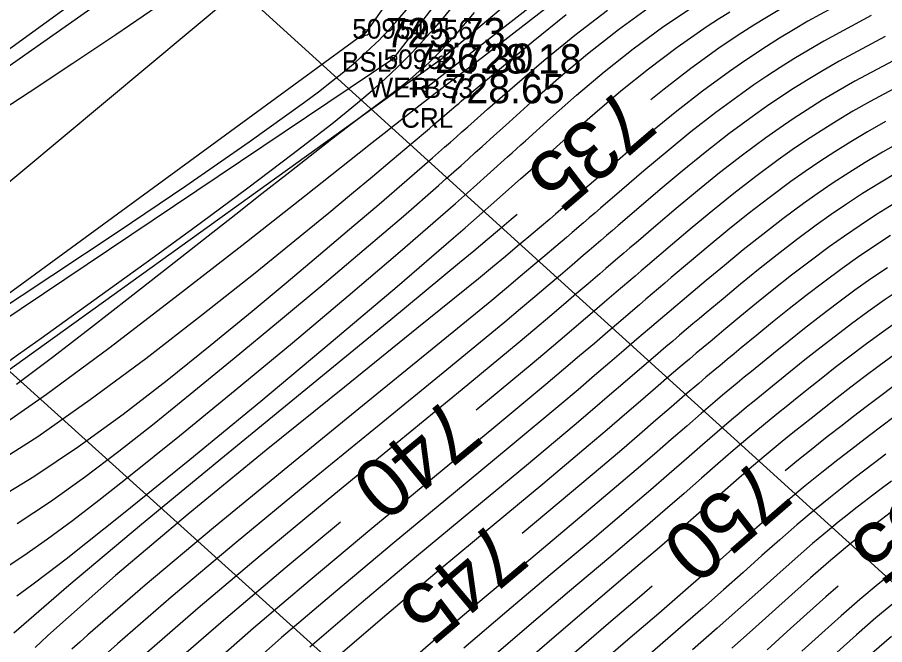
# Model space of a CAD drawing. Extents: x 1378535 to 1380697, y 997729 to 1000024.
# Drawn here: x 1379681.73 to 1379726.06, y 998932.79 to 998964.85 of the extents above; entities that cross this region are included whole.
import ezdxf

# ---------------------------------------------------------------- set-up
doc = ezdxf.new("R2010")
doc.units = 0
for name, color, linetype in [('RD_DTM_BkLn1', 7, 'Continuous'), ('RD_DTM_BkLn2', 7, 'Continuous'), ('RD_DTM_BkLn_txCode', 7, 'Continuous'), ('RD_DTM_Major1', 7, 'Continuous'), ('RD_DTM_Major1_Lbl', 7, 'Continuous'), ('RD_DTM_Minor1', 7, 'Continuous'), ('RD_EX_Bridge', 7, 'Continuous'), ('RD_EX_H2O', 7, 'Continuous'), ('RD_EX_H2O_txCode', 7, 'Continuous'), ('RD_EX_TX_H2O_ELEV', 7, 'Continuous'), ('RD_EX_TX_Misc_ELEV', 7, 'Continuous'), ('RD_SMD_Locator', 7, 'Continuous')]:
    doc.layers.add(name, color=color, linetype=linetype)

msp = doc.modelspace()

# ---------------------------------------------------------------- linework, layer by layer
at = {"layer": 'RD_DTM_BkLn1'}
msp.add_lwpolyline([(1379671.069, 998947.908), (1379694.884, 998967.78), (1379723.442, 999002.448), (1379771.255, 999073.041), (1379827.632, 999138.855), (1379861.249, 999179.195), (1379915.357, 999192.54), (1379973.258, 999207.681), (1380032.706, 999223.017), (1380054.696, 999270.258), (1380073.859, 999314.517)], dxfattribs=at)
at = {"layer": 'RD_DTM_BkLn2'}
for points in [[(1380068.121, 999316.651), (1380049.657, 999274.82), (1380028.513, 999225.034), (1379966.47, 999214.136), (1379918.102, 999198.529), (1379857.342, 999182.9), (1379822.296, 999142.387), (1379766.345, 999075.773), (1379728.069, 999017.429), (1379693.219, 998970.733), (1379663.886, 998950.121)], [(1380081.016, 999311.458), (1380061.411, 999264.141), (1380033.797, 999220.561), (1379978.164, 999199.192), (1379919.041, 999191.309), (1379864.05, 999174.436), (1379831.301, 999133.028), (1379774.735, 999068.751), (1379734.541, 999013.539), (1379699.544, 998964.07), (1379671.775, 998943.782)], [(1379714.915, 998970.843), (1379709.288, 998967.69), (1379703.428, 998962.728), (1379674.221, 998941.737), (1379670.73, 998937.246)]]:
    msp.add_lwpolyline(points, dxfattribs=at)
at = {"layer": 'RD_DTM_Major1'}
for points in [[(1379720.692, 998965.242), (1379720.02, 998964.845), (1379719.377, 998964.452), (1379718.758, 998964.06), (1379718.159, 998963.666), (1379717.575, 998963.268), (1379716.149, 998962.241), (1379714.78, 998961.186), (1379714.107, 998960.638)], [(1379680.379, 998941.917), (1379682.77, 998943.437), (1379685.45, 998945.314), (1379688.286, 998947.419), (1379691.142, 998949.625), (1379693.883, 998951.801), (1379696.373, 998953.82), (1379697.642, 998954.861), (1379698.805, 998955.823), (1379699.881, 998956.72), (1379700.889, 998957.569), (1379701.851, 998958.382), (1379702.786, 998959.176), (1379703.011, 998959.367), (1379703.237, 998959.559), (1379703.463, 998959.752), (1379703.922, 998960.142), (1379704.154, 998960.339), (1379704.286, 998960.451), (1379704.418, 998960.563), (1379704.552, 998960.677), (1379704.687, 998960.791), (1379704.823, 998960.906), (1379704.961, 998961.023), (1379706.465, 998962.288), (1379708.085, 998963.628), (1379709.776, 998964.995)], [(1379727.484, 998961.706), (1379725.315, 998960.552), (1379724.431, 998960.047), (1379723.598, 998959.55), (1379722.809, 998959.057), (1379722.055, 998958.565), (1379721.329, 998958.071), (1379720.623, 998957.571), (1379719.47, 998956.718), (1379718.351, 998955.85), (1379717.269, 998954.978), (1379716.224, 998954.113), (1379715.218, 998953.263), (1379713.933, 998952.168), (1379713.616, 998951.898), (1379713.3, 998951.629), (1379712.983, 998951.358), (1379712.664, 998951.085), (1379712.339, 998950.807), (1379711.74, 998950.292), (1379711.107, 998949.749), (1379710.432, 998949.17), (1379709.701, 998948.547), (1379708.906, 998947.873), (1379708.034, 998947.141), (1379705.266, 998944.843), (1379705.185, 998944.776)], [(1379707.277, 998954.778), (1379706.968, 998954.514), (1379706.377, 998954.011), (1379705.745, 998953.477), (1379705.066, 998952.908), (1379704.333, 998952.296), (1379700.816, 998949.394), (1379692.309, 998942.428), (1379688.077, 998938.937), (1379684.363, 998935.823), (1379681.547, 998933.373)], [(1379726.362, 998953.699), (1379725.501, 998953.137), (1379724.675, 998952.575), (1379723.879, 998952.009), (1379722.947, 998951.323), (1379722.046, 998950.635), (1379721.176, 998949.951), (1379720.333, 998949.274), (1379719.518, 998948.608), (1379718.729, 998947.958), (1379718.367, 998947.66), (1379718.008, 998947.363), (1379717.649, 998947.066), (1379717.289, 998946.765), (1379716.925, 998946.46), (1379716.554, 998946.146), (1379715.867, 998945.557), (1379715.14, 998944.93), (1379714.364, 998944.257), (1379713.528, 998943.533), (1379712.62, 998942.752), (1379711.631, 998941.908), (1379709.422, 998940.051), (1379707.529, 998938.473)], [(1379726.493, 998945.983), (1379725.793, 998945.463), (1379725.116, 998944.952), (1379724.459, 998944.447), (1379723.819, 998943.949), (1379723.191, 998943.456), (1379722.787, 998943.139), (1379722.385, 998942.821), (1379721.981, 998942.499), (1379721.573, 998942.17), (1379721.159, 998941.831), (1379720.975, 998941.678)], [(1379698.241, 998939.051), (1379695.409, 998936.7), (1379692.375, 998934.137), (1379689.851, 998931.935), (1379689.269, 998931.409), (1379688.739, 998930.918), (1379688.255, 998930.459), (1379687.812, 998930.027), (1379687.404, 998929.616), (1379687.025, 998929.222), (1379686.73, 998928.905), (1379686.446, 998928.592), (1379686.17, 998928.28), (1379685.897, 998927.964), (1379685.622, 998927.64), (1379685.342, 998927.305), (1379685.022, 998926.918), (1379684.327, 998926.072), (1379683.945, 998925.605), (1379683.536, 998925.104), (1379683.094, 998924.566), (1379681.167, 998922.234)], [(1379714.179, 998935.777), (1379713.655, 998935.328), (1379711.94, 998933.866), (1379710.187, 998932.366)], [(1379723.678, 998935.784), (1379723.052, 998935.239), (1379722.079, 998934.372), (1379721.077, 998933.466), (1379720.05, 998932.534)]]:
    msp.add_lwpolyline(points, dxfattribs=at)
at = {"layer": 'RD_DTM_Minor1'}
for points in [[(1379724.659, 998966.027), (1379722.137, 998964.652), (1379721.394, 998964.217), (1379720.687, 998963.788), (1379720.012, 998963.363), (1379719.363, 998962.939), (1379718.735, 998962.514), (1379718.122, 998962.084), (1379716.755, 998961.078), (1379715.436, 998960.049), (1379714.164, 998959.011), (1379712.939, 998957.978), (1379711.758, 998956.963), (1379710.622, 998955.979), (1379710.343, 998955.739), (1379710.066, 998955.5), (1379709.789, 998955.262), (1379709.511, 998955.023), (1379709.23, 998954.783), (1379708.946, 998954.541), (1379708.422, 998954.096), (1379707.875, 998953.634), (1379707.296, 998953.148), (1379706.677, 998952.633), (1379706.012, 998952.083), (1379705.291, 998951.491), (1379702.15, 998948.945), (1379698.441, 998945.959), (1379694.449, 998942.73), (1379690.455, 998939.453), (1379686.742, 998936.325), (1379683.592, 998933.542), (1379683.261, 998933.237), (1379682.943, 998932.94), (1379682.635, 998932.649)], [(1379680.899, 998936.59), (1379682.062, 998937.356), (1379683.27, 998938.205), (1379684.541, 998939.145), (1379685.893, 998940.182), (1379687.346, 998941.324), (1379690.006, 998943.46), (1379692.863, 998945.797), (1379695.785, 998948.222), (1379698.64, 998950.622), (1379701.294, 998952.884), (1379703.617, 998954.895), (1379704.117, 998955.334), (1379705.05, 998956.159), (1379705.915, 998956.932), (1379706.787, 998957.717), (1379707.014, 998957.921), (1379707.241, 998958.126), (1379707.467, 998958.331), (1379707.695, 998958.537), (1379708.976, 998959.691), (1379710.314, 998960.871), (1379711.72, 998962.06), (1379713.202, 998963.24), (1379714.77, 998964.395), (1379716.434, 998965.507)], [(1379688.861, 998965.379), (1379686.761, 998963.948), (1379684.566, 998962.485), (1379682.328, 998961.012), (1379680.102, 998959.554)], [(1379680.317, 998940.029), (1379682.577, 998941.389), (1379684.857, 998942.922), (1379687.134, 998944.579), (1379689.385, 998946.316), (1379691.589, 998948.085), (1379693.722, 998949.84), (1379695.459, 998951.285), (1379697.124, 998952.681), (1379698.712, 998954.023), (1379700.216, 998955.306), (1379701.631, 998956.525), (1379702.951, 998957.674), (1379703.257, 998957.943), (1379703.559, 998958.208), (1379703.858, 998958.471), (1379704.155, 998958.733), (1379704.451, 998958.995), (1379704.748, 998959.257), (1379705.081, 998959.552), (1379705.249, 998959.701), (1379705.419, 998959.85), (1379705.762, 998960.153), (1379707.152, 998961.371), (1379708.642, 998962.643), (1379710.222, 998963.937), (1379711.885, 998965.221)], [(1379680.392, 998949.615), (1379683.492, 998951.653), (1379686.886, 998953.909), (1379690.332, 998956.236), (1379693.583, 998958.485), (1379696.396, 998960.508), (1379697.122, 998961.051), (1379697.792, 998961.568), (1379698.412, 998962.065), (1379698.989, 998962.549), (1379699.529, 998963.028), (1379700.038, 998963.508), (1379700.217, 998963.685), (1379700.393, 998963.863), (1379700.566, 998964.043), (1379700.737, 998964.225), (1379700.906, 998964.41), (1379701.074, 998964.597), (1379701.797, 998965.455)], [(1379680.436, 998943.661), (1379683.208, 998945.598), (1379686.397, 998947.952), (1379689.797, 998950.544), (1379693.201, 998953.192), (1379696.406, 998955.713), (1379699.205, 998957.928), (1379699.858, 998958.445), (1379700.474, 998958.932), (1379701.06, 998959.394), (1379701.624, 998959.837), (1379702.171, 998960.265), (1379702.838, 998960.783), (1379703.098, 998960.985), (1379703.228, 998961.085), (1379703.359, 998961.185), (1379703.49, 998961.286), (1379703.563, 998961.342), (1379703.71, 998961.455), (1379703.931, 998961.625), (1379705.495, 998962.816), (1379707.112, 998964.053), (1379708.752, 998965.332)], [(1379680.71, 998946.87), (1379681.786, 998947.638), (1379682.937, 998948.462), (1379684.17, 998949.346), (1379686.376, 998950.931), (1379688.728, 998952.632), (1379691.137, 998954.389), (1379693.511, 998956.144), (1379695.76, 998957.838), (1379697.793, 998959.412), (1379698.526, 998959.996), (1379699.22, 998960.564), (1379699.883, 998961.129), (1379700.527, 998961.703), (1379701.159, 998962.299), (1379701.789, 998962.93), (1379702.206, 998963.368), (1379702.628, 998963.829), (1379703.06, 998964.316), (1379703.504, 998964.832), (1379703.963, 998965.381)], [(1379681.685, 998946.104), (1379683.515, 998947.49), (1379685.467, 998948.987), (1379687.484, 998950.548), (1379689.509, 998952.127), (1379691.485, 998953.677), (1379692.89, 998954.783), (1379694.23, 998955.84), (1379695.5, 998956.84), (1379696.692, 998957.774), (1379697.802, 998958.636), (1379698.822, 998959.417), (1379699.525, 998959.948), (1379700.181, 998960.44), (1379700.794, 998960.904), (1379701.371, 998961.352), (1379701.918, 998961.795), (1379702.44, 998962.244), (1379702.598, 998962.386), (1379702.754, 998962.531), (1379702.91, 998962.678), (1379703.064, 998962.828), (1379703.219, 998962.981), (1379703.374, 998963.139), (1379703.783, 998963.573), (1379704.201, 998964.042), (1379704.633, 998964.55), (1379705.085, 998965.099)], [(1379681.699, 998935.291), (1379682.468, 998935.853), (1379683.304, 998936.481), (1379684.22, 998937.184), (1379687.157, 998939.505), (1379690.551, 998942.256), (1379694.166, 998945.238), (1379697.771, 998948.252), (1379701.133, 998951.097), (1379704.018, 998953.575), (1379704.624, 998954.101), (1379705.192, 998954.597), (1379706.237, 998955.517), (1379707.452, 998956.595), (1379707.958, 998957.047), (1379709.955, 998958.829), (1379711.243, 998959.956), (1379712.581, 998961.089), (1379713.98, 998962.216), (1379715.447, 998963.322), (1379716.99, 998964.396), (1379717.558, 998964.768), (1379718.14, 998965.136)], [(1379681.713, 998938.982), (1379683.42, 998940.116), (1379685.15, 998941.353), (1379686.911, 998942.685), (1379688.714, 998944.102), (1379690.566, 998945.594), (1379692.811, 998947.426), (1379695.079, 998949.301), (1379697.314, 998951.169), (1379699.459, 998952.983), (1379701.456, 998954.694), (1379703.248, 998956.255), (1379703.647, 998956.607), (1379704.033, 998956.949), (1379704.408, 998957.283), (1379704.774, 998957.61), (1379705.134, 998957.934), (1379705.489, 998958.254), (1379705.687, 998958.432), (1379705.884, 998958.611), (1379706.081, 998958.789), (1379706.679, 998959.33), (1379707.995, 998960.516), (1379709.39, 998961.742), (1379710.874, 998962.986), (1379712.456, 998964.229), (1379714.145, 998965.449)], [(1379725.376, 998964.941), (1379722.943, 998963.627), (1379722.159, 998963.173), (1379721.417, 998962.725), (1379720.709, 998962.282), (1379720.03, 998961.84), (1379719.374, 998961.396), (1379718.734, 998960.947), (1379717.424, 998959.982), (1379716.157, 998958.996), (1379714.935, 998958.002), (1379713.756, 998957.012), (1379712.622, 998956.041), (1379711.533, 998955.1), (1379711.243, 998954.85), (1379710.956, 998954.602), (1379710.668, 998954.354), (1379710.089, 998953.857), (1379709.795, 998953.604), (1379709.252, 998953.14), (1379708.683, 998952.655), (1379708.079, 998952.144), (1379707.431, 998951.599), (1379706.732, 998951.015), (1379705.972, 998950.384), (1379702.93, 998947.892), (1379699.365, 998944.994), (1379695.549, 998941.886), (1379691.756, 998938.769), (1379688.259, 998935.839), (1379685.333, 998933.295), (1379684.915, 998932.918), (1379684.518, 998932.555)], [(1379726.08, 998963.863), (1379723.737, 998962.605), (1379722.917, 998962.133), (1379722.142, 998961.667), (1379721.406, 998961.207), (1379720.701, 998960.747), (1379720.02, 998960.285), (1379719.356, 998959.818), (1379718.102, 998958.893), (1379716.888, 998957.948), (1379715.714, 998956.996), (1379714.581, 998956.049), (1379713.491, 998955.119), (1379712.445, 998954.218), (1379712.144, 998953.96), (1379711.846, 998953.703), (1379711.549, 998953.448), (1379710.949, 998952.933), (1379710.643, 998952.671), (1379710.08, 998952.187), (1379709.487, 998951.681), (1379708.856, 998951.144), (1379708.178, 998950.569), (1379707.442, 998949.95), (1379706.638, 998949.28), (1379703.674, 998946.836), (1379700.221, 998944.012), (1379696.547, 998941.005), (1379692.915, 998938.009), (1379689.592, 998935.221), (1379686.842, 998932.837), (1379686.365, 998932.409)], [(1379726.782, 998962.785), (1379724.527, 998961.58), (1379723.674, 998961.091), (1379722.869, 998960.609), (1379722.106, 998960.131), (1379721.376, 998959.655), (1379720.672, 998959.177), (1379719.986, 998958.693), (1379718.784, 998957.804), (1379717.619, 998956.899), (1379716.491, 998955.987), (1379715.403, 998955.081), (1379714.356, 998954.192), (1379713.351, 998953.331), (1379713.04, 998953.065), (1379712.733, 998952.802), (1379712.426, 998952.539), (1379711.807, 998952.009), (1379711.492, 998951.739), (1379710.91, 998951.239), (1379710.297, 998950.713), (1379709.642, 998950.154), (1379708.937, 998949.555), (1379708.169, 998948.907), (1379707.33, 998948.203), (1379704.459, 998945.827), (1379701.138, 998943.099), (1379697.616, 998940.206), (1379694.143, 998937.331), (1379690.968, 998934.661), (1379688.342, 998932.379)], [(1379726.101, 998959.522), (1379725.188, 998959.003), (1379724.328, 998958.491), (1379723.514, 998957.983), (1379722.738, 998957.476), (1379721.99, 998956.967), (1379721.265, 998956.453), (1379720.158, 998955.634), (1379719.086, 998954.803), (1379718.047, 998953.97), (1379717.045, 998953.144), (1379716.079, 998952.333), (1379715.151, 998951.547), (1379714.822, 998951.268), (1379714.497, 998950.992), (1379714.172, 998950.717), (1379713.847, 998950.44), (1379713.519, 998950.16), (1379713.185, 998949.875), (1379712.568, 998949.346), (1379711.917, 998948.786), (1379711.221, 998948.188), (1379710.468, 998947.544), (1379709.647, 998946.846), (1379708.746, 998946.087), (1379706.087, 998943.873), (1379703.051, 998941.366), (1379699.851, 998938.722), (1379696.697, 998936.094), (1379693.799, 998933.637), (1379691.369, 998931.505)], [(1379726.886, 998958.491), (1379725.946, 998957.958), (1379725.06, 998957.433), (1379724.223, 998956.911), (1379723.424, 998956.389), (1379722.656, 998955.866), (1379721.912, 998955.337), (1379720.851, 998954.552), (1379719.823, 998953.758), (1379718.827, 998952.964), (1379717.866, 998952.176), (1379716.939, 998951.402), (1379716.047, 998950.652), (1379715.71, 998950.368), (1379715.376, 998950.086), (1379715.043, 998949.805), (1379714.372, 998949.236), (1379714.03, 998948.943), (1379713.396, 998948.399), (1379712.726, 998947.823), (1379712.01, 998947.206), (1379711.235, 998946.541), (1379710.39, 998945.821), (1379709.463, 998945.038), (1379706.914, 998942.911), (1379704.027, 998940.521), (1379700.991, 998938.006), (1379697.997, 998935.503), (1379695.235, 998933.151), (1379692.895, 998931.087)], [(1379726.703, 998956.914), (1379725.794, 998956.375), (1379724.933, 998955.839), (1379724.113, 998955.304), (1379723.326, 998954.767), (1379722.563, 998954.225), (1379721.547, 998953.473), (1379720.562, 998952.715), (1379719.609, 998951.958), (1379718.688, 998951.208), (1379717.799, 998950.471), (1379716.942, 998949.755), (1379716.596, 998949.466), (1379716.254, 998949.179), (1379715.913, 998948.892), (1379715.57, 998948.603), (1379715.224, 998948.31), (1379714.872, 998948.011), (1379714.221, 998947.453), (1379713.533, 998946.859), (1379712.797, 998946.224), (1379712.001, 998945.539), (1379711.133, 998944.797), (1379710.184, 998943.993), (1379707.747, 998941.955), (1379705.008, 998939.682), (1379702.136, 998937.297), (1379699.303, 998934.92), (1379696.677, 998932.673)], [(1379726.53, 998955.317), (1379725.647, 998954.768), (1379724.806, 998954.22), (1379723.999, 998953.67), (1379723.219, 998953.116), (1379722.245, 998952.397), (1379721.303, 998951.674), (1379720.392, 998950.954), (1379719.51, 998950.24), (1379718.659, 998949.54), (1379717.836, 998948.857), (1379717.482, 998948.563), (1379717.131, 998948.271), (1379716.781, 998947.979), (1379716.43, 998947.684), (1379716.075, 998947.385), (1379715.714, 998947.079), (1379715.045, 998946.505), (1379714.338, 998945.895), (1379713.582, 998945.241), (1379712.765, 998944.536), (1379711.877, 998943.775), (1379710.906, 998942.949), (1379708.583, 998941.001), (1379705.993, 998938.847), (1379703.286, 998936.592), (1379700.612, 998934.341), (1379698.122, 998932.2)], [(1379726.199, 998952.056), (1379725.354, 998951.481), (1379724.541, 998950.905), (1379723.651, 998950.251), (1379722.792, 998949.597), (1379721.961, 998948.949), (1379721.157, 998948.307), (1379720.378, 998947.676), (1379719.621, 998947.059), (1379719.251, 998946.756), (1379718.884, 998946.455), (1379718.516, 998946.152), (1379718.147, 998945.846), (1379717.773, 998945.534), (1379717.393, 998945.213), (1379716.687, 998944.609), (1379715.941, 998943.963), (1379715.145, 998943.271), (1379714.289, 998942.528), (1379713.363, 998941.729), (1379712.357, 998940.868), (1379710.263, 998939.102), (1379707.969, 998937.183), (1379705.588, 998935.186), (1379703.232, 998933.186), (1379701.015, 998931.26)], [(1379726.899, 998950.977), (1379726.036, 998950.39), (1379725.207, 998949.803), (1379724.358, 998949.181), (1379723.539, 998948.561), (1379722.748, 998947.948), (1379721.981, 998947.342), (1379721.238, 998946.745), (1379720.514, 998946.159), (1379720.135, 998945.852), (1379719.759, 998945.546), (1379719.383, 998945.239), (1379719.004, 998944.927), (1379718.621, 998944.608), (1379718.23, 998944.28), (1379717.505, 998943.66), (1379716.739, 998942.996), (1379715.923, 998942.285), (1379715.048, 998941.523), (1379714.105, 998940.705), (1379713.084, 998939.829), (1379711.107, 998938.156), (1379708.96, 998936.353), (1379706.738, 998934.482), (1379704.54, 998932.607)], [(1379726.721, 998949.3), (1379725.876, 998948.703), (1379725.067, 998948.113), (1379724.288, 998947.527), (1379723.536, 998946.948), (1379722.807, 998946.376), (1379722.098, 998945.813), (1379721.406, 998945.258), (1379721.019, 998944.948), (1379720.634, 998944.638), (1379720.249, 998944.326), (1379719.861, 998944.008), (1379719.468, 998943.683), (1379719.067, 998943.346), (1379718.321, 998942.71), (1379717.535, 998942.028), (1379716.699, 998941.298), (1379715.806, 998940.517), (1379714.847, 998939.682), (1379713.814, 998938.792), (1379711.954, 998937.211), (1379709.952, 998935.523), (1379707.889, 998933.778), (1379705.845, 998932.026)], [(1379726.548, 998947.606), (1379725.779, 998947.047), (1379725.039, 998946.494), (1379724.325, 998945.949), (1379723.633, 998945.411), (1379722.958, 998944.881), (1379722.298, 998944.357), (1379721.903, 998944.044), (1379721.51, 998943.729), (1379721.115, 998943.412), (1379720.718, 998943.089), (1379720.314, 998942.757), (1379719.902, 998942.413), (1379719.136, 998941.761), (1379718.329, 998941.06), (1379717.473, 998940.31), (1379716.562, 998939.51), (1379715.588, 998938.659), (1379714.546, 998937.756), (1379712.803, 998936.268), (1379710.945, 998934.694), (1379709.038, 998933.073), (1379707.148, 998931.443)], [(1379726.548, 998944.434), (1379725.908, 998943.955), (1379725.287, 998943.483), (1379724.681, 998943.017), (1379724.085, 998942.555), (1379723.672, 998942.235), (1379723.26, 998941.912), (1379722.847, 998941.586), (1379722.428, 998941.251), (1379722.003, 998940.906), (1379721.569, 998940.546), (1379720.76, 998939.86), (1379719.91, 998939.12), (1379719.014, 998938.331), (1379717.071, 998936.613), (1379716.017, 998935.69), (1379714.511, 998934.39), (1379712.937, 998933.039), (1379711.335, 998931.657)], [(1379726.117, 998942.52), (1379725.544, 998942.085), (1379724.98, 998941.654), (1379724.558, 998941.33), (1379724.137, 998941.004), (1379723.712, 998940.673), (1379723.283, 998940.332), (1379722.847, 998939.98), (1379722.4, 998939.612), (1379721.57, 998938.909), (1379720.698, 998938.15), (1379719.782, 998937.341), (1379718.822, 998936.487), (1379717.814, 998935.591), (1379716.757, 998934.66), (1379715.371, 998933.454), (1379713.936, 998932.213)], [(1379726.409, 998941.155), (1379725.878, 998940.754), (1379725.446, 998940.427), (1379725.014, 998940.096), (1379724.578, 998939.76), (1379724.138, 998939.414), (1379723.69, 998939.055), (1379723.231, 998938.679), (1379722.378, 998937.958), (1379721.484, 998937.179), (1379720.549, 998936.351), (1379719.573, 998935.479), (1379718.557, 998934.571), (1379717.501, 998933.633), (1379716.235, 998932.522)], [(1379726.336, 998939.524), (1379725.892, 998939.19), (1379725.445, 998938.848), (1379724.993, 998938.496), (1379724.533, 998938.13), (1379724.061, 998937.746), (1379723.185, 998937.007), (1379722.268, 998936.209), (1379721.314, 998935.361), (1379719.302, 998933.551), (1379718.249, 998932.608)], [(1379726.22, 998936.282), (1379725.722, 998935.882), (1379724.797, 998935.107), (1379723.836, 998934.27), (1379722.844, 998933.384), (1379721.83, 998932.462)], [(1379726.554, 998934.952), (1379725.605, 998934.16), (1379724.62, 998933.303), (1379723.611, 998932.397)], [(1379726.416, 998933.215), (1379725.409, 998932.338)]]:
    msp.add_lwpolyline(points, dxfattribs=at)
at = {"layer": 'RD_EX_Bridge'}
for points in [[(1379637.224, 998986.549), (1379644.844, 998995.13), (1379652.407, 999003.171), (1379729.964, 998932.802)], [(1379637.224, 998986.549), (1379715.012, 998916.385), (1379722.406, 998924.582), (1379729.964, 998932.802)]]:
    msp.add_lwpolyline(points, dxfattribs=at)
at = {"layer": 'RD_EX_H2O'}
for points in [[(1379663.754, 998950.515), (1379692.381, 998971.287), (1379719.043, 999005.745), (1379767.054, 999077.466), (1379820.322, 999142.061), (1379856.776, 999184.172), (1379909.653, 999199.365), (1379968.411, 999216.307), (1380029.427, 999227.408), (1380049.406, 999276.128), (1380067.001, 999316.436)], [(1379671.834, 998943.202), (1379700.963, 998962.761), (1379729.374, 998999.597), (1379746.583, 999025.229), (1379775.663, 999068.698), (1379833.361, 999132.972), (1379865.604, 999174.536), (1379921.646, 999184.161), (1379977.925, 999198.092), (1380034.402, 999218.74), (1380062.356, 999262.9), (1380081.879, 999311.699)], [(1379702.564, 998961.21), (1379714.915, 998970.843), (1379740.261, 998989.569), (1379744.315, 999002.648), (1379747.404, 999008.004), (1379748.702, 999008.829), (1379750.233, 999010.437), (1379755.456, 999017.171), (1379756.704, 999019.626), (1379779.044, 999063.15), (1379837.226, 999126.786), (1379869.284, 999172.186), (1379924.949, 999180.924)]]:
    msp.add_lwpolyline(points, dxfattribs=at)
at = {"layer": 'RD_SMD_Locator'}
for centre in [(1379699.544, 998964.07), (1379700.963, 998962.761), (1379700.963, 998962.761), (1379703.428, 998962.728), (1379702.564, 998961.21)]:
    msp.add_circle(centre, 0.15, dxfattribs=at)

# ---------------------------------------------------------------- texts
at = {"layer": 'RD_DTM_BkLn_txCode'}
for s, p in [('50956', (1379701.286, 998963.728)), ('BSL', (1379698.316, 998962.07)), ('+BS3', (1379701.711, 998960.728))]:
    msp.add_text(s, height=1, dxfattribs=at).set_placement(p)
at = {"layer": 'RD_DTM_Major1_Lbl'}
for s, rotation, p in [('735', 220.6352, (1379712.622, 998961.372)), ('740', 219.5001, (1379703.765, 998945.551)), ('750', 220.9693, (1379719.534, 998942.418)), ('755', 217.1973, (1379729.389, 998942.146)), ('745', 220.1719, (1379706.088, 998939.246))]:
    msp.add_text(s, height=3, rotation=rotation, dxfattribs=at).set_placement(p)
at = {"layer": 'RD_EX_H2O_txCode'}
for s, p in [('50954', (1379698.845, 998963.761)), ('50954', (1379698.845, 998963.761)), ('50955', (1379700.446, 998962.21)), ('WER', (1379699.672, 998960.761)), ('WER', (1379699.672, 998960.761)), ('CRL', (1379701.336, 998959.21))]:
    msp.add_text(s, height=1, dxfattribs=at).set_placement(p)
at = {"layer": 'RD_EX_TX_H2O_ELEV'}
for s, p in [('726.30', (1379701.963, 998962.011)), ('726.30', (1379701.963, 998962.011)), ('728.65', (1379703.564, 998960.46))]:
    msp.add_text(s, height=1.5, dxfattribs=at).set_placement(p)
at = {"layer": 'RD_EX_TX_Misc_ELEV'}
for s, p in [('725.73', (1379700.544, 998963.32)), ('728.18', (1379704.428, 998961.978))]:
    msp.add_text(s, height=1.5, dxfattribs=at).set_placement(p)

doc.saveas('drawing.dxf')
